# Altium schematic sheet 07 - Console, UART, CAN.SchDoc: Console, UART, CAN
size A3; PageSetup: Record=PageOptions¦CenterHorizontal=True¦CenterVertical=True¦PrintScale=0.70¦XCorrection=1.00¦YCorrection=1.00¦PrintKind=0¦BorderSize=5000000¦LeftOffset=0¦BottomOffset=0¦Orientation=2¦PaperLength=4200¦PaperWidth=2970¦Scale=100¦PaperSource=7¦PrintQuality=600¦MediaType=1¦DitherType=10¦PaperKind=A4¦PrintScaleMode=1; Author: Juan Anzola; SheetNumber: 7; SheetTotal: 17
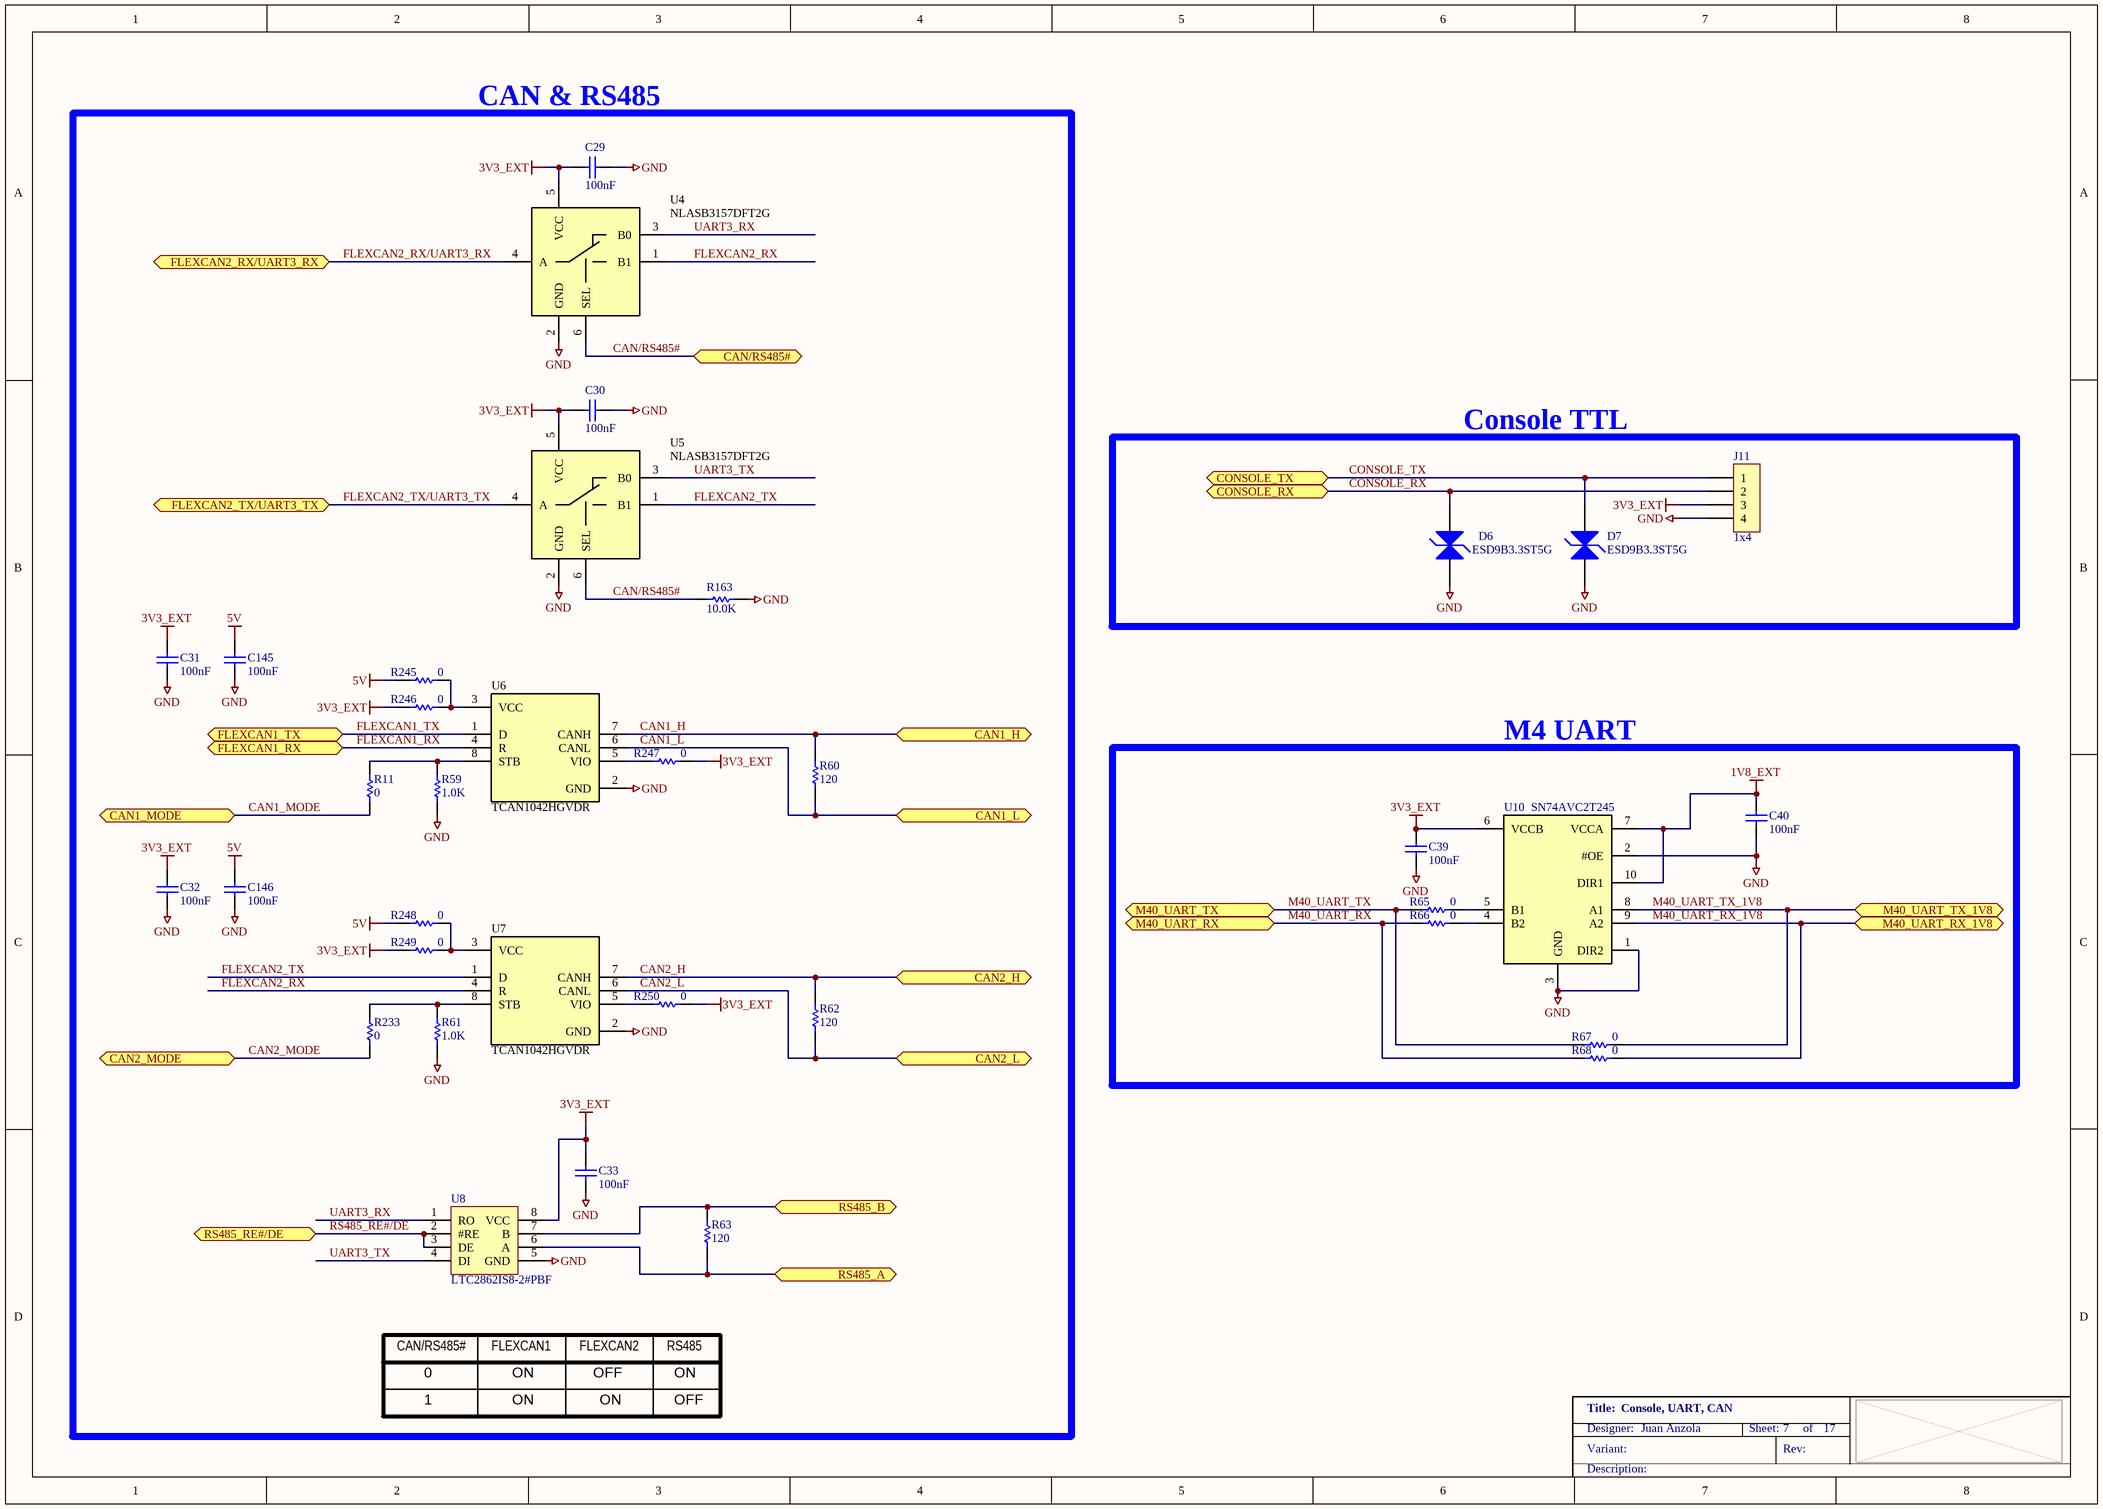
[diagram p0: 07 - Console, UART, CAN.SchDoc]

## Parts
C29  100nF  [CAPC1005X55N]
C30  100nF  [CAPC1005X55N]
C31  100nF  [CAPC1005X55N]
C32  100nF  [CAPC1005X55N]
C33  100nF  [CAPC1005X55N]
C39  100nF  [CAPC1005X55N]
C40  100nF  [CAPC1005X55N]
C145  100nF  [CAPC1005X55N]
C146  100nF  [CAPC1005X55N]
D6  ESD9B3.3ST5G  [SODFL1006X43AN12]
D7  ESD9B3.3ST5G  [SODFL1006X43AN12]
J11  1x4  [MOLEX_53047-0410]
R11  0  [RESC1005X40N]
R59  1.0K  [RESC1005X40N]
R60  120  [RESC1005X40N]
R61  1.0K  [RESC1005X40N]
R62  120  [RESC1005X40N]
R63  120  [RESC1005X40N]
R65  0  [RESC1005X40N]
R66  0  [RESC1005X40N]
R67  0  [RESC1005X40N]
R68  0  [RESC1005X40N]
R163  10.0K  [RESC1005X40N]
R233  0  [RESC1005X40N]
R245  0  [RESC1005X40N]
R246  0  [RESC1005X40N]
R247  0  [RESC1005X40N]
R248  0  [RESC1005X40N]
R249  0  [RESC1005X40N]
R250  0  [RESC1005X40N]
U4  NLASB3157DFT2G  [SOT65P210X110-6N]
U5  NLASB3157DFT2G  [SOT65P210X110-6N]
U6  TCAN1042HGVDR  [SOIC127P600X175-8N]
U7  TCAN1042HGVDR  [SOIC127P600X175-8N]
U8  LTC2862IS8-2#PBF  [SOIC127P600X175-8N]
U10  SN74AVC2T245  [QFN40P180X140X55-10N]

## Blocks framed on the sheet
CAN & RS485: C29-C33 C145 C146 R11 R59-R63 R163 R233 R245-R250 U4-U8
Console TTL: D6 D7 J11
M4 UART: C39 C40 R65-R68 U10

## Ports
CAN1_H (bidir), CAN1_L (bidir), CAN1_MODE (bidir), CAN2_H (bidir), CAN2_L (bidir), CAN2_MODE (bidir), CAN/RS485# (bidir), CONSOLE_RX (bidir), CONSOLE_TX (bidir), FLEXCAN1_RX (bidir), FLEXCAN1_TX (bidir), FLEXCAN2_RX/UART3_RX (bidir), FLEXCAN2_TX/UART3_TX (bidir), M40_UART_RX (bidir), M40_UART_RX_1V8 (bidir), M40_UART_TX (bidir), M40_UART_TX_1V8 (bidir), RS485_A (bidir), RS485_B (bidir), RS485_RE#/DE (bidir)

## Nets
1V8_EXT: C40.2 U10.7(VCCA) U10.10(DIR1)
3V3_EXT: C29.1 C30.1 C31.2 C32.2 C33.2 C39.2 J11.3 R246.1 R247.2 R249.1 R250.2 U4.5(VCC) U5.5(VCC) U8.8(VCC) U10.6(VCCB)
5V: C145.2 C146.2 R245.1 R248.1
GND: C29.2 C30.2 C31.1 C32.1 C33.1 C39.1 C40.1 C145.1 C146.1 D6.1 D7.1 J11.4 R59.1 R61.1 R163.2 U4.2(GND) U5.2(GND) U6.2(GND) U7.2(GND) U8.5(GND) U10.1(DIR2) U10.2(#OE) U10.3(GND)
CAN1_H: R60.2 U6.7(CANH) ; port CAN1_H
CAN1_L: R60.1 U6.6(CANL) ; port CAN1_L
CAN1_MODE: R11.1 ; port CAN1_MODE
CAN2_H: R62.2 U7.7(CANH) ; port CAN2_H
CAN2_L: R62.1 U7.6(CANL) ; port CAN2_L
CAN2_MODE: R233.1 ; port CAN2_MODE
CAN/RS485#: R163.1 U4.6(SEL) U5.6(SEL) ; port CAN/RS485#
CONSOLE_RX: D6.2 J11.2 ; port CONSOLE_RX
CONSOLE_TX: D7.2 J11.1 ; port CONSOLE_TX
FLEXCAN1_RX: U6.4(R) ; port FLEXCAN1_RX
FLEXCAN1_TX: U6.1(D) ; port FLEXCAN1_TX
FLEXCAN2_RX: U4.1(B1) U7.4(R)
FLEXCAN2_RX/UART3_RX: U4.4(A) ; port FLEXCAN2_RX/UART3_RX
FLEXCAN2_TX: U5.1(B1) U7.1(D)
FLEXCAN2_TX/UART3_TX: U5.4(A) ; port FLEXCAN2_TX/UART3_TX
M40_UART_RX: R66.1 R68.1 ; port M40_UART_RX
M40_UART_RX_1V8: R68.2 U10.9(A2) ; port M40_UART_RX_1V8
M40_UART_TX: R65.1 R67.1 ; port M40_UART_TX
M40_UART_TX_1V8: R67.2 U10.8(A1) ; port M40_UART_TX_1V8
RS485_A: R63.1 U8.6(A) ; port RS485_A
RS485_B: R63.2 U8.7(B) ; port RS485_B
RS485_RE#/DE: U8.2(#RE) U8.3(DE) ; port RS485_RE#/DE
UART3_RX: U4.3(B0) U8.1(RO)
UART3_TX: U5.3(B0) U8.4(DI)
NetR11_2: R11.2 R59.2 U6.8(STB)
NetR61_2: R61.2 R233.2 U7.8(STB)
NetR65_2: R65.2 U10.5(B1)
NetR66_2: R66.2 U10.4(B2)
NetR245_2: R245.2 R246.2 U6.3(VCC)
NetR247_1: R247.1 U6.5(VIO)
NetR248_2: R248.2 R249.2 U7.3(VCC)
NetR250_1: R250.1 U7.5(VIO)

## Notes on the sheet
- CAN/RS485#
- 0
- FLEXCAN1
- ON
- FLEXCAN2
- OFF
- RS485
- 1

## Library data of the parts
C29 C30 C39 C40 = 1000006: CAP 100nF 16V 10% X7R 0402; Part_Type: Capacitor; Manufacturer: Murata; Manufacturer_Part_Number: GRM155R71C104KA88D; Digi_PN: 14050552; Component_Life_Cycle_State: CAD Reviewed; Area: 0,95; Project: KITT; Tolerance: 10
C31-C33 C145 C146 = 1000006: CAP 100nF 16V 10% X7R 0402; Part_Type: Capacitor; Manufacturer: Murata; Manufacturer_Part_Number: GRM155R71C104KA88D; Component_Life_Cycle_State: CAD Reviewed; Area: 0.95; Project: KITT; Tolerance: 10; Digi_PN: 14050552
D6 D7 = 1001637: TVS DIODE 3.3VWM SOD923; Part_Type: Diodes; Manufacturer: On Semiconductor; Digi_PN: 17050883; Component_Life_Cycle_State: Reviewed; Area: 1,01; Project: CareTaker IV
J11 = 1001137: CONN HEADER 4POS 1.25MM VERT TIN; Part_Type: Connector; Manufacturer: Molex; Manufacturer_Part_Number: 53047-0410; Digi_PN: 18050344; Component_Life_Cycle_State: Reviewed; Area: 21.6; Project: CCWMX6_SBC board
R11 R65-R68 R233 = 1000076: RES 0.0 OHM 1/10W 0402 SMD; Part_Type: Resistor; Manufacturer: Panasonic - ECG; Manufacturer_Part_Number: ERJ-2GE0R00X; Digi_PN: 13050387; Component_Life_Cycle_State: Proven; Area: 0,95; Project: Adjustable Foundation; Power_WV_SRF: 10
R59 R61 = 1000079: RES 1.00K OHM 1/10W 1% 0402 SMD; Part_Type: Resistor; Manufacturer: Panasonic - ECG; Manufacturer_Part_Number: ERJ-2RKF1001X; Digi_PN: 13051085; Component_Life_Cycle_State: Proven; Area: 0,95; Project: Adjustable Foundation; Power_WV_SRF: 10
R60 R62 R63 = 1001158: RES 120 OHM 1/16W 1% 0402 SMD; Part_Type: Resistor; Manufacturer: Yageo; Manufacturer_Part_Number: RC0402FR-07120RL; Digi_PN: 13050832; Component_Life_Cycle_State: Reviewed; Area: 0.95; Project: CCWMX6_SBC board; Note: 13051102 = Digi No. for GE WDNU
R163 = 1000537: RES 10.0K OHM 1/10W 1% 0402 SMD; Part_Type: Resistor; Manufacturer: Panasonic - ECG; Manufacturer_Part_Number: ERJ-2RKF1002X; Component_Life_Cycle_State: CAD Reviewed; Area: 0.95; Project: KITT; Power_WV_SRF: 100; Digi_PN: 13051084
R245-R250 = 1000076: RES 0.0 OHM 1/10W 0402 SMD; Part_Type: Resistor; Manufacturer: Panasonic - ECG; Manufacturer_Part_Number: ERJ-2GE0R00X; Component_Life_Cycle_State: Proven; Area: 0.95; Project: Adjustable Foundation; Power_WV_SRF: 10; Digi_PN: 13050387
U4 U5 = 1001179: IC SWITCH SPDT SC88; Manufacturer: On Semiconductor; Digi_PN: 16051954; Component_Life_Cycle_State: Reviewed; Area: 4,8; Project: CCWMX6_SBC board
U6 U7 = 1002681: IC CAN TRANSEIVER HS 8SOIC; Manufacturer: Texas Instruments; Digi_PN: 16000166; Component_Life_Cycle_State: Pending; Area: 20; Project: DIGI CC8X SOM
U8 = 1001420: IC TRANSCEIVER RS485 8-SOIC; Manufacturer: Linear Technology; Digi_PN: 16052092; Component_Life_Cycle_State: Reviewed; Area: 34.75; Project: E-Gear Gateway v0.1
U10 = 1002531: IC BUS TRANSCVR TRI-ST DL 10UQFN; Manufacturer: Texas Instruments; Manufacturer_Part_Number: SN74AVC2T245RSWR; Digi_PN: 16052024; Component_Life_Cycle_State: Created; Area: 8.01; Project: DIGI CC8X SOM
